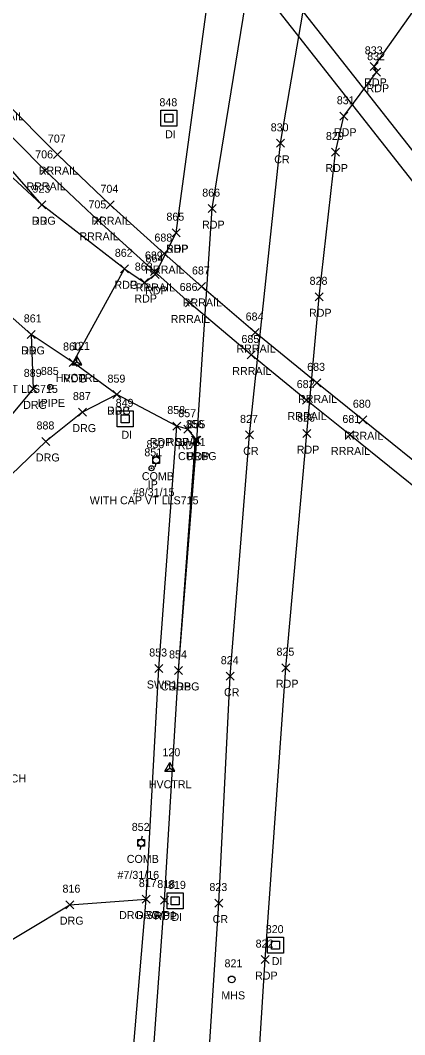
# Model space of a CAD drawing. Extents: x 1615599 to 1619911, y 273782 to 280437.
# Drawn here: x 1616473.7 to 1616569.8, y 279589.5 to 279843.1 of the extents above; entities that cross this region are included whole.
import ezdxf

# ---------------------------------------------------------------- set-up
doc = ezdxf.new("R2010")
doc.units = 0
for name, color, linetype in [('C_A', 7, 'Continuous'), ('C_I', 7, 'Continuous'), ('CPSM', 7, 'Continuous'), ('D_A', 7, 'Continuous'), ('D_I', 7, 'Continuous'), ('DS', 7, 'Continuous'), ('L_A', 7, 'Continuous'), ('M_A', 7, 'Continuous'), ('M_C', 7, 'Continuous'), ('M_I', 7, 'Continuous'), ('MPIP', 7, 'Continuous'), ('MPIR', 7, 'Continuous'), ('P_A', 7, 'Continuous'), ('P_I', 7, 'Continuous'), ('P_TIC', 7, 'Continuous'), ('PET', 7, 'Continuous'), ('PEU', 7, 'Continuous'), ('PRC', 7, 'Continuous'), ('PSP', 7, 'Continuous'), ('R_A', 7, 'Continuous'), ('R_I', 7, 'Continuous'), ('R_TIC', 7, 'Continuous'), ('RC', 7, 'Continuous'), ('RDG', 7, 'Continuous'), ('RR', 7, 'Continuous'), ('RSW', 7, 'Continuous'), ('U_A', 7, 'Continuous'), ('U_C', 7, 'Continuous'), ('U_I', 7, 'Continuous'), ('UP', 7, 'Continuous'), ('USMH', 7, 'Continuous')]:
    doc.layers.add(name, color=color, linetype=linetype)

msp = doc.modelspace()

# ---------------------------------------------------------------- linework, layer by layer
at = {"layer": 'CPSM'}
for p, q in [((1616486.58, 279756.99), (1616487.83, 279759.16)), ((1616486.58, 279756.99), (1616487.83, 279757.72)), ((1616486.58, 279756.99), (1616489.08, 279756.99)), ((1616489.08, 279756.99), (1616487.83, 279759.16)), ((1616487.83, 279757.72), (1616487.83, 279759.16)), ((1616487.83, 279757.72), (1616487.83, 279757.72)), ((1616487.83, 279757.72), (1616489.08, 279756.99)), ((1616509.86, 279655.4), (1616511.11, 279657.57)), ((1616509.86, 279655.4), (1616511.11, 279656.12)), ((1616509.86, 279655.4), (1616512.36, 279655.4)), ((1616512.36, 279655.4), (1616511.11, 279657.57)), ((1616511.11, 279656.12), (1616511.11, 279657.57)), ((1616511.11, 279656.12), (1616511.11, 279656.12)), ((1616511.11, 279656.12), (1616512.36, 279655.4))]:
    msp.add_line(p, q, dxfattribs=at)
at = {"layer": 'DS'}
for p, q in [((1616508.84, 279820.62), (1616512.84, 279820.62)), ((1616508.84, 279816.62), (1616508.84, 279820.62)), ((1616512.84, 279820.62), (1616512.84, 279816.62)), ((1616509.84, 279817.62), (1616509.84, 279819.62)), ((1616509.84, 279819.62), (1616511.84, 279819.62)), ((1616510.84, 279818.62), (1616510.84, 279818.62)), ((1616510.84, 279818.62), (1616510.84, 279818.62)), ((1616511.84, 279819.62), (1616511.84, 279817.62)), ((1616512.84, 279816.62), (1616508.84, 279816.62)), ((1616511.84, 279817.62), (1616509.84, 279817.62)), ((1616497.91, 279745.48), (1616501.91, 279745.48)), ((1616497.91, 279741.48), (1616497.91, 279745.48)), ((1616498.91, 279742.48), (1616498.91, 279744.48)), ((1616498.91, 279744.48), (1616500.91, 279744.48)), ((1616500.91, 279744.48), (1616500.91, 279742.48)), ((1616501.91, 279745.48), (1616501.91, 279741.48)), ((1616500.91, 279742.48), (1616498.91, 279742.48)), ((1616499.91, 279743.48), (1616499.91, 279743.48)), ((1616499.91, 279743.48), (1616499.91, 279743.48)), ((1616501.91, 279741.48), (1616497.91, 279741.48)), ((1616510.43, 279624.96), (1616514.43, 279624.96)), ((1616510.43, 279620.96), (1616510.43, 279624.96)), ((1616514.43, 279624.96), (1616514.43, 279620.96)), ((1616511.43, 279621.96), (1616511.43, 279623.96)), ((1616511.43, 279623.96), (1616513.43, 279623.96)), ((1616512.44, 279622.97), (1616512.44, 279622.97)), ((1616512.44, 279622.97), (1616512.44, 279622.97)), ((1616513.43, 279623.96), (1616513.43, 279621.96)), ((1616514.43, 279620.96), (1616510.43, 279620.96)), ((1616513.43, 279621.96), (1616511.43, 279621.96)), ((1616535.51, 279613.9), (1616539.51, 279613.9)), ((1616535.51, 279609.9), (1616535.51, 279613.9)), ((1616536.51, 279610.9), (1616536.51, 279612.9)), ((1616536.51, 279612.9), (1616538.51, 279612.9)), ((1616538.51, 279612.9), (1616538.51, 279610.9)), ((1616539.51, 279613.9), (1616539.51, 279609.9)), ((1616539.51, 279609.9), (1616535.51, 279609.9)), ((1616538.51, 279610.9), (1616536.51, 279610.9)), ((1616537.52, 279611.9), (1616537.52, 279611.9)), ((1616537.52, 279611.9), (1616537.52, 279611.9))]:
    msp.add_line(p, q, dxfattribs=at)
at = {"layer": 'MPIP'}
for radius in [0.625, 0.0833]:
    msp.add_circle((1616481.19, 279751.45), radius, dxfattribs=at)
at = {"layer": 'MPIR'}
for radius in [0.625, 0.0833]:
    msp.add_circle((1616506.51, 279731.11), radius, dxfattribs=at)
at = {"layer": 'P_TIC'}
for points in [[(1616561.2, 279830.59), (1616563.2, 279832.59)], [(1616563.2, 279830.59), (1616561.2, 279832.59)], [(1616561.79, 279829.13), (1616563.79, 279831.13)], [(1616563.79, 279829.13), (1616561.79, 279831.13)], [(1616553.63, 279818.12), (1616555.63, 279820.12)], [(1616555.63, 279818.12), (1616553.63, 279820.12)], [(1616537.76, 279811.35), (1616539.76, 279813.35)], [(1616539.76, 279811.35), (1616537.76, 279813.35)], [(1616551.49, 279809.18), (1616553.49, 279811.18)], [(1616553.49, 279809.18), (1616551.49, 279811.18)], [(1616478.11, 279796), (1616480.11, 279798)], [(1616480.11, 279796), (1616478.11, 279798)], [(1616520.66, 279795.02), (1616522.66, 279797.02)], [(1616522.66, 279795.02), (1616520.66, 279797.02)], [(1616511.64, 279789.01), (1616513.64, 279791.01)], [(1616513.64, 279789.01), (1616511.64, 279791.01)], [(1616511.64, 279789.01), (1616513.64, 279791.01)], [(1616513.64, 279789.01), (1616511.64, 279791.01)], [(1616498.74, 279779.98), (1616500.74, 279781.98)], [(1616500.74, 279779.98), (1616498.74, 279781.98)], [(1616498.74, 279779.98), (1616500.74, 279781.98)], [(1616500.74, 279779.98), (1616498.74, 279781.98)], [(1616506.42, 279778.59), (1616508.42, 279780.59)], [(1616508.42, 279778.59), (1616506.42, 279780.59)], [(1616503.73, 279776.54), (1616505.73, 279778.54)], [(1616505.73, 279776.54), (1616503.73, 279778.54)], [(1616547.4, 279772.98), (1616549.4, 279774.98)], [(1616549.4, 279772.98), (1616547.4, 279774.98)], [(1616475.4, 279763.58), (1616477.4, 279765.58)], [(1616477.4, 279763.58), (1616475.4, 279765.58)], [(1616485.88, 279756.56), (1616487.88, 279758.56)], [(1616487.88, 279756.56), (1616485.88, 279758.56)], [(1616485.88, 279756.56), (1616487.88, 279758.56)], [(1616487.88, 279756.56), (1616485.88, 279758.56)], [(1616496.87, 279748.53), (1616498.87, 279750.53)], [(1616498.87, 279748.53), (1616496.87, 279750.53)], [(1616511.82, 279740.67), (1616513.82, 279742.67)], [(1616513.82, 279740.67), (1616511.82, 279742.67)], [(1616514.56, 279739.89), (1616516.56, 279741.89)], [(1616516.56, 279739.89), (1616514.56, 279741.89)], [(1616516.86, 279737.11), (1616518.86, 279739.11)], [(1616518.86, 279737.11), (1616516.86, 279739.11)], [(1616516.86, 279737.11), (1616518.86, 279739.11)], [(1616518.86, 279737.11), (1616516.86, 279739.11)], [(1616530, 279738.46), (1616532, 279740.46)], [(1616532, 279738.46), (1616530, 279740.46)], [(1616544.34, 279738.77), (1616546.34, 279740.77)], [(1616546.34, 279738.77), (1616544.34, 279740.77)], [(1616512.26, 279679.58), (1616514.26, 279681.58)], [(1616514.26, 279679.58), (1616512.26, 279681.58)], [(1616539.12, 279680.26), (1616541.12, 279682.26)], [(1616541.12, 279680.26), (1616539.12, 279682.26)], [(1616525.18, 279678.14), (1616527.18, 279680.14)], [(1616527.18, 279678.14), (1616525.18, 279680.14)], [(1616508.74, 279622.18), (1616510.74, 279624.18)], [(1616510.74, 279622.18), (1616508.74, 279624.18)], [(1616522.34, 279621.43), (1616524.34, 279623.43)], [(1616524.34, 279621.43), (1616522.34, 279623.43)], [(1616533.9, 279607.29), (1616535.9, 279609.29)], [(1616535.9, 279607.29), (1616533.9, 279609.29)]]:
    msp.add_lwpolyline(points, dxfattribs=at)
at = {"layer": 'PET'}
for points in [[(1616501.73, 279478.79), (1616504.15, 279516.53), (1616502.36, 279521.09), (1616509.74, 279623.18), (1616513.26, 279680.58), (1616517.86, 279738.11), (1616521.66, 279796.02), (1616535.31, 279880.04), (1616539.68, 279905.35), (1616550.57, 279973.08)], [(1616526.87, 279479.75), (1616534.9, 279608.29), (1616540.12, 279681.26), (1616545.34, 279739.77), (1616548.4, 279773.98), (1616552.49, 279810.18), (1616554.63, 279819.12), (1616562.79, 279830.13), (1616562.2, 279831.59), (1616577.14, 279852.75), (1616589.88, 279863.08), (1616620.87, 279876.82)], [(1616517.86, 279738.11), (1616515.56, 279740.89), (1616512.82, 279741.67), (1616497.87, 279749.53), (1616486.88, 279757.56), (1616499.74, 279780.98), (1616504.73, 279777.54), (1616507.42, 279779.59), (1616512.64, 279790.01)]]:
    msp.add_lwpolyline(points, dxfattribs=at)
at = {"layer": 'PEU'}
for points in [[(1616499.74, 279780.98), (1616479.11, 279797), (1616319.46, 279945.62), (1616274.32, 279994.35), (1616255.18, 280018.22), (1616235.11, 280063.13), (1616219.63, 280113.45), (1616199.45, 280157.82), (1616176.87, 280194.27), (1616140.8, 280248.09)], [(1616486.88, 279757.56), (1616476.4, 279764.58), (1616449.89, 279788.09), (1616430.61, 279808), (1616410.01, 279827.22), (1616355.68, 279874.73), (1616329.14, 279895.83), (1616251.77, 279973.13), (1616240.04, 279993.6), (1616211.88, 280076.79), (1616204.14, 280097.8), (1616191.71, 280134.04), (1616179.76, 280157.24), (1616153.69, 280197.29), (1616148.4, 280204.31)]]:
    msp.add_lwpolyline(points, dxfattribs=at)
at = {"layer": 'PRC'}
msp.add_lwpolyline([(1616513.97, 279478.68), (1616523.34, 279622.43), (1616526.18, 279679.14), (1616531, 279739.46), (1616538.76, 279812.35), (1616562.87, 279952.64)], dxfattribs=at)
at = {"layer": 'PSP'}
msp.add_lwpolyline([(1616512.64, 279790.01), (1616522.19, 279859.94), (1616511.98, 279872.39), (1616522.04, 279879.79), (1616527.95, 279872.59), (1616535.31, 279880.04)], dxfattribs=at)
at = {"layer": 'R_TIC'}
for points in [[(1616482.02, 279808.54), (1616484.02, 279810.54)], [(1616484.02, 279808.54), (1616482.02, 279810.54)], [(1616478.92, 279804.59), (1616480.92, 279806.59)], [(1616480.92, 279804.59), (1616478.92, 279806.59)], [(1616478.11, 279796), (1616480.11, 279798)], [(1616480.11, 279796), (1616478.11, 279798)], [(1616495.17, 279795.99), (1616497.17, 279797.99)], [(1616497.17, 279795.99), (1616495.17, 279797.99)], [(1616492.17, 279792.09), (1616494.17, 279794.09)], [(1616494.17, 279792.09), (1616492.17, 279794.09)], [(1616508.64, 279783.79), (1616510.64, 279785.79)], [(1616510.64, 279783.79), (1616508.64, 279785.79)], [(1616506.27, 279779.31), (1616508.27, 279781.31)], [(1616508.27, 279779.31), (1616506.27, 279781.31)], [(1616518.03, 279775.56), (1616520.03, 279777.56)], [(1616520.03, 279775.56), (1616518.03, 279777.56)], [(1616515, 279771.44), (1616517, 279773.44)], [(1616517, 279771.44), (1616515, 279773.44)], [(1616475.4, 279763.58), (1616477.4, 279765.58)], [(1616477.4, 279763.58), (1616475.4, 279765.58)], [(1616531.45, 279764.05), (1616533.45, 279766.05)], [(1616533.45, 279764.05), (1616531.45, 279766.05)], [(1616530.41, 279758.44), (1616532.41, 279760.44)], [(1616532.41, 279758.44), (1616530.41, 279760.44)], [(1616475.92, 279749.96), (1616477.92, 279751.96)], [(1616477.92, 279749.96), (1616475.92, 279751.96)], [(1616546.84, 279751.47), (1616548.84, 279753.47)], [(1616548.84, 279751.47), (1616546.84, 279753.47)], [(1616496.87, 279748.53), (1616498.87, 279750.53)], [(1616498.87, 279748.53), (1616496.87, 279750.53)], [(1616544.23, 279747.16), (1616546.23, 279749.16)], [(1616546.23, 279747.16), (1616544.23, 279749.16)], [(1616488.21, 279744.16), (1616490.21, 279746.16)], [(1616490.21, 279744.16), (1616488.21, 279746.16)], [(1616558.36, 279742.25), (1616560.36, 279744.25)], [(1616560.36, 279742.25), (1616558.36, 279744.25)], [(1616511.82, 279740.67), (1616513.82, 279742.67)], [(1616513.82, 279740.67), (1616511.82, 279742.67)], [(1616516.54, 279737.16), (1616518.54, 279739.16)], [(1616518.54, 279737.16), (1616516.54, 279739.16)], [(1616555.08, 279738.45), (1616557.08, 279740.45)], [(1616557.08, 279738.45), (1616555.08, 279740.45)], [(1616479.11, 279736.82), (1616481.11, 279738.82)], [(1616481.11, 279736.82), (1616479.11, 279738.82)], [(1616507.3, 279680.06), (1616509.3, 279682.06)], [(1616509.3, 279680.06), (1616507.3, 279682.06)], [(1616512.26, 279679.58), (1616514.26, 279681.58)], [(1616514.26, 279679.58), (1616512.26, 279681.58)], [(1616485.09, 279621.02), (1616487.09, 279623.02)], [(1616487.09, 279621.02), (1616485.09, 279623.02)], [(1616504.13, 279622.42), (1616506.13, 279624.42)], [(1616506.13, 279622.42), (1616504.13, 279624.42)], [(1616504.13, 279622.42), (1616506.13, 279624.42)], [(1616506.13, 279622.42), (1616504.13, 279624.42)]]:
    msp.add_lwpolyline(points, dxfattribs=at)
at = {"layer": 'RC'}
msp.add_lwpolyline([(1616513.26, 279680.58), (1616517.54, 279738.16)], dxfattribs=at)
at = {"layer": 'RDG'}
for points in [[(1616479.11, 279797), (1616452.08, 279827.9), (1616424.38, 279862.23), (1616403.84, 279893.76), (1616381.28, 279930.94), (1616358.21, 279967.76), (1616328.46, 279952.33), (1616323.53, 279951.52)], [(1616476.4, 279764.58), (1616476.92, 279750.96), (1616468.44, 279740.89), (1616429.63, 279704.65), (1616403.63, 279679.78), (1616362.98, 279636.29), (1616328.32, 279610.24), (1616263.33, 279567.8)], [(1616497.87, 279749.53), (1616489.21, 279745.16), (1616480.11, 279737.82), (1616436.78, 279696.31), (1616411.24, 279672.61), (1616387.47, 279642.06), (1616397.28, 279621.61), (1616371.82, 279603.44), (1616356.02, 279618.85), (1616332.01, 279604.55), (1616287.77, 279573.66), (1616275.48, 279563.53), (1616266.66, 279551.67)], [(1616496.49, 279521.23), (1616475.87, 279524.73), (1616446.46, 279536.69), (1616430.6, 279554.8), (1616420.14, 279572.99), (1616452.75, 279601.95), (1616486.09, 279622.02), (1616505.13, 279623.42)]]:
    msp.add_lwpolyline(points, dxfattribs=at)
at = {"layer": 'RR'}
for points in [[(1618863.67, 276894.43), (1618803.13, 276971.25), (1618287.89, 277627.49), (1618272.16, 277647.46), (1617630.42, 278463.6), (1617620.37, 278476.22), (1617582.75, 278523.92), (1617266.97, 278926.89), (1616715.35, 279628.09), (1616637.52, 279726.94), (1616590.36, 279786.85), (1616151.06, 280346.19)], [(1618859.75, 276891.53), (1618799.24, 276968.15), (1618284.94, 277623.12), (1618268.81, 277643.64), (1617626.81, 278460.24), (1617616.13, 278473.64), (1617546.95, 278561.72), (1617499.49, 278621.79), (1617406.55, 278740.52), (1617357.63, 278802.9), (1617271.97, 278912.55), (1616838.51, 279463.88), (1616791.25, 279524.04), (1616711.4, 279625.23), (1616195.43, 280281.84), (1616147.06, 280342.91)], [(1616578.78, 279727.56), (1616559.36, 279743.25), (1616547.84, 279752.47), (1616532.45, 279765.05), (1616519.03, 279776.56), (1616509.64, 279784.79), (1616496.17, 279796.99), (1616483.02, 279809.54), (1616469.51, 279823.1), (1616459.09, 279834.19), (1616449.19, 279845.4), (1616437.84, 279859.03), (1616423.84, 279877.95), (1616413.56, 279893.5), (1616402.73, 279911.89), (1616392.59, 279930.69), (1616381.25, 279953.2), (1616368.15, 279979.78), (1616347.86, 280021.18)], [(1616575.93, 279723.48), (1616556.08, 279739.45), (1616545.23, 279748.16), (1616531.41, 279759.44), (1616516, 279772.44), (1616507.27, 279780.31), (1616493.17, 279793.09), (1616479.92, 279805.59), (1616465.51, 279820.07), (1616455.17, 279831.23), (1616445.64, 279841.88), (1616433.79, 279856.11), (1616419.63, 279875.14), (1616409.64, 279890.58), (1616398.5, 279909.46), (1616388.61, 279927.52), (1616376.81, 279951.06), (1616363.7, 279977.75), (1616343.37, 280019.21)]]:
    msp.add_lwpolyline(points, dxfattribs=at)
at = {"layer": 'RSW'}
msp.add_lwpolyline([(1616494.27, 279479.6), (1616496.49, 279521.23), (1616505.13, 279623.42), (1616508.3, 279681.06), (1616512.82, 279741.67)], dxfattribs=at)
at = {"layer": 'UP'}
for p, q in [((1616506.87, 279732.31), (1616506.87, 279733.98)), ((1616506.87, 279733.98), (1616508.53, 279733.98)), ((1616507.95, 279734.81), (1616507.7, 279733.98)), ((1616508.53, 279733.98), (1616508.53, 279732.31)), ((1616508.53, 279732.31), (1616506.87, 279732.31)), ((1616507.45, 279731.48), (1616507.7, 279732.31)), ((1616507.7, 279733.14), (1616507.7, 279733.14)), ((1616503.09, 279636.63), (1616503.09, 279638.29)), ((1616503.09, 279638.29), (1616504.76, 279638.29)), ((1616504.17, 279639.13), (1616503.92, 279638.29)), ((1616504.76, 279638.29), (1616504.76, 279636.63)), ((1616504.76, 279636.63), (1616503.09, 279636.63)), ((1616503.67, 279635.79), (1616503.92, 279636.63)), ((1616503.92, 279637.46), (1616503.92, 279637.46))]:
    msp.add_line(p, q, dxfattribs=at)
for centre in [(1616507.7, 279733.14), (1616503.92, 279637.46)]:
    msp.add_circle(centre, 0.833, dxfattribs=at)
at = {"layer": 'USMH'}
for p, q in [((1616526.55, 279603.35), (1616526.55, 279603.35)), ((1616527.39, 279603.35), (1616527.39, 279603.35))]:
    msp.add_line(p, q, dxfattribs=at)
msp.add_circle((1616526.55, 279603.35), 0.833, dxfattribs=at)

# ---------------------------------------------------------------- texts
at = {"layer": 'C_A'}
for p in [(1616482.53, 279752.72), (1616505.81, 279651.12)]:
    msp.add_text('HVCTRL', height=2, dxfattribs=at).set_placement(p)
at = {"layer": 'C_I'}
for s, p in [('121', (1616486.61, 279760.72)), ('120', (1616509.23, 279659.12))]:
    msp.add_text(s, height=2, dxfattribs=at).set_placement(p)
at = {"layer": 'D_A'}
for p in [(1616509.9, 279813.62), (1616498.97, 279738.48), (1616511.49, 279617.97), (1616536.57, 279606.9)]:
    msp.add_text('DI', height=2, dxfattribs=at).set_placement(p)
at = {"layer": 'D_I'}
for s, p in [('848', (1616508.48, 279821.62)), ('849', (1616497.54, 279746.48)), ('819', (1616510.63, 279625.97)), ('820', (1616535.07, 279614.9))]:
    msp.add_text(s, height=2, dxfattribs=at).set_placement(p)
at = {"layer": 'L_A'}
msp.add_text('PORCH', height=2, dxfattribs=at).set_placement((1616465.47, 279652.58))
at = {"layer": 'M_A'}
for s, p in [('IPIPE', (1616478.03, 279746.45)), ('IP', (1616505.55, 279726.11))]:
    msp.add_text(s, height=2, dxfattribs=at).set_placement(p)
at = {"layer": 'M_C'}
for p in [(1616455.88, 279749.96), (1616491.06, 279722.11)]:
    msp.add_text('WITH CAP VT LLS715', height=2, dxfattribs=at).set_placement(p)
at = {"layer": 'M_I'}
for s, p in [('885', (1616478.83, 279754.45)), ('851', (1616504.71, 279734.11))]:
    msp.add_text(s, height=2, dxfattribs=at).set_placement(p)
at = {"layer": 'P_A'}
for s, p in [('RDP', (1616559.69, 279826.59)), ('RDP', (1616560.28, 279825.13)), ('RDP', (1616552.12, 279814.12)), ('CR', (1616537.19, 279807.35)), ('RDP', (1616549.97, 279805.18)), ('RDG', (1616476.59, 279792)), ('RDP', (1616519.14, 279791.02)), ('SHP', (1616510.17, 279785.01)), ('RDP', (1616510.12, 279785.01)), ('RDG', (1616497.23, 279775.98)), ('RDP', (1616497.23, 279775.98)), ('RDP', (1616502.21, 279772.54)), ('RDP', (1616504.9, 279774.59)), ('RDP', (1616545.89, 279768.98)), ('RDG', (1616473.89, 279759.58)), ('RDG', (1616484.37, 279752.56)), ('RDP', (1616484.37, 279752.56)), ('RDP', (1616495.36, 279744.53)), ('RDP', (1616510.3, 279736.67)), ('RDP', (1616513.05, 279735.89)), ('CR', (1616529.43, 279734.46)), ('RDP', (1616542.82, 279734.77)), ('RDP', (1616515.35, 279733.11)), ('RDP', (1616515.35, 279733.11)), ('RDP', (1616537.61, 279676.26)), ('RDP', (1616510.74, 279675.58)), ('CR', (1616524.62, 279674.14)), ('RDP', (1616507.22, 279618.18)), ('CR', (1616521.78, 279617.43)), ('RDP', (1616532.39, 279603.29))]:
    msp.add_text(s, height=2, dxfattribs=at).set_placement(p)
at = {"layer": 'P_I'}
for s, p in [('833', (1616559.84, 279834.59)), ('832', (1616560.43, 279833.13)), ('831', (1616552.84, 279822.12)), ('830', (1616536.31, 279815.35)), ('829', (1616550.12, 279813.18)), ('923', (1616476.74, 279800)), ('866', (1616519.19, 279799.02)), ('865', (1616510.23, 279793.01)), ('865', (1616510.23, 279793.01)), ('862', (1616497.33, 279783.98)), ('862', (1616497.33, 279783.98)), ('863', (1616502.32, 279780.54)), ('864', (1616505.01, 279782.59)), ('828', (1616546.04, 279776.98)), ('861', (1616474.56, 279767.58)), ('860', (1616484.38, 279760.56)), ('860', (1616484.38, 279760.56)), ('859', (1616495.5, 279752.53)), ('858', (1616510.45, 279744.67)), ('857', (1616513.2, 279743.89)), ('827', (1616528.64, 279742.46)), ('826', (1616542.92, 279742.77)), ('855', (1616515.5, 279741.11)), ('855', (1616515.5, 279741.11)), ('825', (1616537.76, 279684.26)), ('854', (1616510.89, 279683.58)), ('824', (1616523.82, 279682.14)), ('818', (1616507.94, 279626.18)), ('823', (1616520.98, 279625.43)), ('822', (1616532.54, 279611.29))]:
    msp.add_text(s, height=2, dxfattribs=at).set_placement(p)
at = {"layer": 'R_A'}
for s, p in [('RRRAIL', (1616464.8, 279818.1)), ('RRRAIL', (1616478.32, 279804.54)), ('RRRAIL', (1616475.21, 279800.59)), ('DRG', (1616476.59, 279792)), ('RRRAIL', (1616491.46, 279791.99)), ('RRRAIL', (1616488.46, 279788.09)), ('RRRAIL', (1616504.93, 279779.79)), ('RRRAIL', (1616502.56, 279775.31)), ('RRRAIL', (1616514.32, 279771.56)), ('RRRAIL', (1616511.29, 279767.44)), ('RRRAIL', (1616527.74, 279760.05)), ('DRG', (1616473.89, 279759.58)), ('RRRAIL', (1616526.7, 279754.44)), ('RRRAIL', (1616543.13, 279747.47)), ('DRG', (1616474.41, 279745.96)), ('DRG', (1616495.36, 279744.53)), ('RRRAIL', (1616540.52, 279743.16)), ('DRG', (1616486.7, 279740.16)), ('RRRAIL', (1616554.65, 279738.25)), ('RDP SWP1', (1616506.08, 279736.67)), ('DRG', (1616477.59, 279732.82)), ('CURBG', (1616513.13, 279733.16)), ('RRRAIL', (1616551.38, 279734.45)), ('SWP1', (1616505.33, 279676.06)), ('CURBG', (1616508.84, 279675.58)), ('DRG SWP1', (1616498.39, 279618.42)), ('DRG', (1616502.62, 279618.42)), ('DRG', (1616483.58, 279617.02))]:
    msp.add_text(s, height=2, dxfattribs=at).set_placement(p)
at = {"layer": 'R_I'}
for s, p in [('707', (1616480.58, 279812.54)), ('706', (1616477.42, 279808.59)), ('923', (1616476.74, 279800)), ('704', (1616493.73, 279799.99)), ('705', (1616490.73, 279796.09)), ('688', (1616507.23, 279787.79)), ('689', (1616504.85, 279783.31)), ('687', (1616516.62, 279779.56)), ('686', (1616513.54, 279775.44)), ('861', (1616474.56, 279767.58)), ('684', (1616530.04, 279768.05)), ('685', (1616529, 279762.44)), ('683', (1616545.43, 279755.47)), ('889', (1616474.55, 279753.96)), ('859', (1616495.5, 279752.53)), ('682', (1616542.82, 279751.16)), ('887', (1616486.85, 279748.16)), ('858', (1616510.45, 279744.67)), ('680', (1616556.86, 279746.25)), ('681', (1616554.24, 279742.45)), ('888', (1616477.74, 279740.82)), ('856', (1616515.13, 279741.16)), ('853', (1616505.93, 279684.06)), ('854', (1616510.89, 279683.58)), ('817', (1616503.33, 279626.42)), ('817', (1616503.33, 279626.42)), ('816', (1616484.24, 279625.02))]:
    msp.add_text(s, height=2, dxfattribs=at).set_placement(p)
at = {"layer": 'U_A'}
for s, p in [('COMB', (1616504.09, 279728.14)), ('COMB', (1616500.31, 279632.46)), ('MHS', (1616523.97, 279598.35))]:
    msp.add_text(s, height=2, dxfattribs=at).set_placement(p)
at = {"layer": 'U_C'}
for s, p in [('#8/31/15', (1616501.83, 279724.14)), ('#7/31/16', (1616497.99, 279628.46))]:
    msp.add_text(s, height=2, dxfattribs=at).set_placement(p)
at = {"layer": 'U_I'}
for s, p in [('850', (1616505.25, 279736.14)), ('852', (1616501.56, 279640.46)), ('821', (1616524.76, 279606.35))]:
    msp.add_text(s, height=2, dxfattribs=at).set_placement(p)

doc.saveas('drawing.dxf')
